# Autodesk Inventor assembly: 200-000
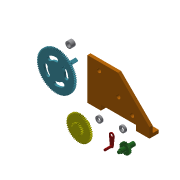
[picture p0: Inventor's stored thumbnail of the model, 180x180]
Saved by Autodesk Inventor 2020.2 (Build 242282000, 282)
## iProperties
Created: 2014-01
Part Number: 200-000
Document SubType Name: Assembly
Designer: F.Stasiak
Manager: www.cadconsulting.pl
Company: Fabian Stasiak CAD Consulting
Author: F.Stasiak
Subject: Zbiór ćwiczeń. Autodesk Inventor 2020. Kurs podstawowy
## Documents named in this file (8)
- C:\2020_Kurs_podstawowy\R6 Zespoły\Warsztat\200-000.iam
- C:\2020_Kurs_podstawowy\R6 Zespoły\Warsztat\Komponenty\200-001.ipt
- C:\2020_Kurs_podstawowy\R6 Zespoły\Warsztat\Komponenty\200-004.ipt
- C:\2020_Kurs_podstawowy\R6 Zespoły\Warsztat\Komponenty\200-003.ipt
- C:\2020_Kurs_podstawowy\R6 Zespoły\Warsztat\Komponenty\200-006.ipt
- C:\2020_Kurs_podstawowy\R6 Zespoły\Warsztat\Komponenty\200-007.ipt
- C:\2020_Kurs_podstawowy\R6 Zespoły\Warsztat\Komponenty\200-005.ipt
- C:\2020_Kurs_podstawowy\R6 Zespoły\Warsztat\Komponenty\200-002.ipt
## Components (8 placed, 7 different names)
1. 200-001:1
2. 200-006:1
3. 200-006:2
4. 200-007:1
5. Koło z=20
6. Koło z=20/51
7. Koło z=80
8. 200-005:1
